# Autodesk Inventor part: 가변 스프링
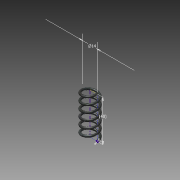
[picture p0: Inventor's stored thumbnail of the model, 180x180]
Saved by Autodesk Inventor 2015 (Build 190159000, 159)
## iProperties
Created: 2020-02
Part Number: 가변 스프링
Material: 강철
Document SubType Name: Modeling
Designer: LINEART-A501
Density: 7.85 g/cm^3
Appearance: 플레이트
Mass: 6.50802 g
Surface Area: 16.7391 cm^2
Volume: 0.829047 cm^3
Author: LINEART-A501
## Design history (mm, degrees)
sketch "스케치1"
  geometry: L1 (0, 0)-(7, 0); L2 (7, 0)-(7, 40); L3 (7, 40)-(0, 40); L4 (0, 40)-(0, 0); C1 r 1 at (7, 0)
  constraints: 8 end point, 2 parallel, 1 centre point, 1 coincident, 1 horizontal, 1 perpendicular
  dimensions: "d0" = 14 diameter of L2 L4; "d1" = 40 distance of L1.end L2.end (derived); "d2" = 2 diameter of C1
feature "코일1" pitch "d3" = 10; turns "d5" = 6; dims "d4" = 40 (= d1), "d6" = 0, angle "d7" = 90 deg, angle "d8" = 90 deg, "d9" = 0, "d10" = 0
node "솔리드1"
